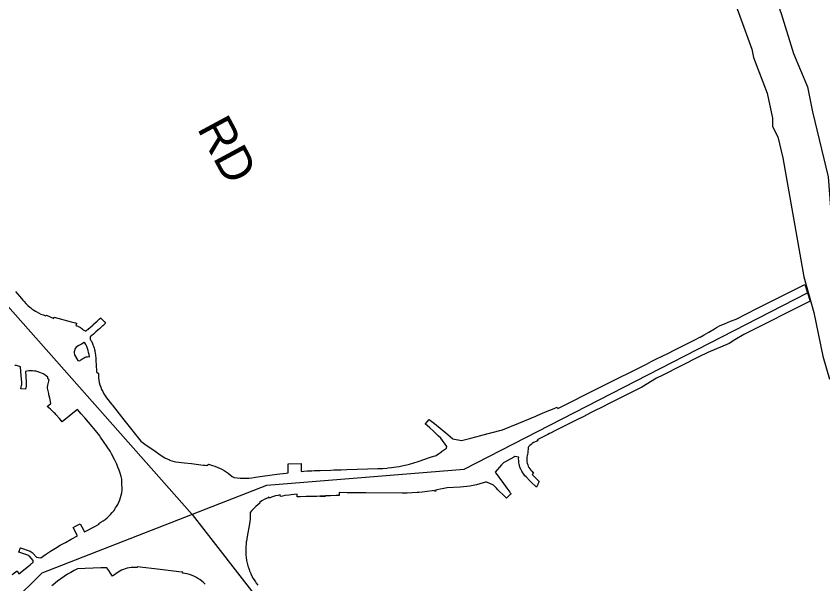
# Model space of a CAD drawing. Extents: x 1936118 to 1997618, y 780614 to 828614.
# Drawn here: x 1963667 to 1977726, y 800516 to 810402 of the extents above; entities that cross this region are included whole.
import ezdxf

# ---------------------------------------------------------------- set-up
doc = ezdxf.new("R2010")
doc.units = 0
for name, color, linetype in [('RD_EX_H2O_BlueLn', 7, 'Continuous'), ('RD_SHT_Misc3', 7, 'Continuous'), ('RD_SHT_Misc4', 7, 'Continuous')]:
    doc.layers.add(name, color=color, linetype=linetype)

msp = doc.modelspace()

# ---------------------------------------------------------------- linework, layer by layer
at = {"layer": 'RD_EX_H2O_BlueLn'}
for points in [[(1973253, 817137), (1973407, 816991), (1973584, 816594), (1973887, 815756), (1974339, 815098), (1974706, 814408), (1974918, 814125), (1975309, 813500), (1975457, 813315), (1975643, 812956), (1976517, 811570), (1976734, 811173), (1977001, 810446), (1977217, 809753), (1977458, 809171), (1977548, 808736), (1977820, 807606), (1977875, 806845), (1977998, 806260), (1978211, 805465), (1978363, 805022), (1978540, 804151), (1978567, 804110), (1978671, 803787)], [(1976212, 810593), (1976486, 809828), (1976516, 809681), (1976758, 809064), (1976848, 808628), (1976848, 808483), (1976942, 808300), (1977030, 807934), (1977392, 805863), (1977569, 805242), (1977724, 804480), (1977843, 804082)], [(1963654, 805609), (1963689, 805568), (1963692, 805566), (1963731, 805521), (1963787, 805456), (1963808, 805432), (1963839, 805398), (1963871, 805366), (1963905, 805336), (1963923, 805322), (1963941, 805307), (1963978, 805281), (1964006, 805264), (1964017, 805257), (1964057, 805235), (1964098, 805215), (1964140, 805198), (1964183, 805183), (1964198, 805195), (1964322, 805139), (1964332, 805162), (1964626, 805081), (1964700, 805061), (1964722, 805054), (1964721, 805051), (1964709, 805016), (1964709, 805016), (1964714, 805014), (1964716, 805014), (1964722, 805012), (1964724, 805011), (1964741, 805003), (1964749, 805000), (1964751, 804999), (1964766, 804991), (1964776, 804985), (1964788, 804978), (1964790, 804976), (1964799, 804970), (1964812, 804960), (1964821, 804953), (1964824, 804950), (1964833, 804942), (1964845, 804931), (1964880, 804914), (1964908, 804937), (1964920, 804948), (1964936, 804961), (1964966, 804989), (1965004, 805023), (1965012, 805030), (1965012, 805030), (1965077, 805089), (1965092, 805102), (1965117, 805124), (1965144, 805148), (1965151, 805139), (1965205, 805077), (1965205, 805077), (1965225, 805053), (1965200, 805030), (1965176, 805010), (1965175, 805009), (1965119, 804958), (1965093, 804935), (1965057, 804902), (1965026, 804874), (1965020, 804869), (1965013, 804863), (1965013, 804863), (1964989, 804842), (1964958, 804816), (1964958, 804813), (1964958, 804795), (1964958, 804778), (1964972, 804752), (1964978, 804740), (1964996, 804701), (1965002, 804687), (1965002, 804686), (1965012, 804661), (1965014, 804657), (1965014, 804655), (1965026, 804620), (1965031, 804600), (1965037, 804579), (1965040, 804565), (1965045, 804542), (1965045, 804537), (1965052, 804495), (1965052, 804488), (1965055, 804452), (1965057, 804416), (1965057, 804413), (1965069, 804227), (1965070, 804209), (1965105, 804177), (1965104, 804152), (1965103, 804105), (1965108, 804063), (1965117, 804022), (1965128, 803981), (1965141, 803941), (1965157, 803902), (1965166, 803885), (1965176, 803864), (1965196, 803827), (1965219, 803792), (1965244, 803758), (1965330, 803648), (1965343, 803632), (1965547, 803373), (1965843, 802998), (1965934, 802933), (1966065, 802842), (1966177, 802762), (1966259, 802710), (1966299, 802691), (1966340, 802673), (1966343, 802672), (1966382, 802658), (1966423, 802645), (1966450, 802641), (1966602, 802624), (1966721, 802610), (1966886, 802591), (1966931, 802585), (1966961, 802581), (1966992, 802576), (1967020, 802598), (1967088, 802578), (1967130, 802565), (1967172, 802549), (1967213, 802532), (1967252, 802512), (1967291, 802491), (1967329, 802467), (1967365, 802442), (1967400, 802415), (1967434, 802387), (1967468, 802367), (1967519, 802361), (1967570, 802357), (1967621, 802355), (1967672, 802356), (1967724, 802359), (1967775, 802365), (1967837, 802373), (1968211, 802424), (1968373, 802446), (1968408, 802450), (1968408, 802451), (1968410, 802561), (1968411, 802608), (1968633, 802610), (1968634, 802563), (1968634, 802562), (1968635, 802475), (1968683, 802478), (1968742, 802482), (1968819, 802487), (1968868, 802489), (1968909, 802490), (1968968, 802492), (1969154, 802498), (1969204, 802499), (1969330, 802503), (1969333, 802503), (1969429, 802506), (1969971, 802522), (1970050, 802525), (1970130, 802532), (1970149, 802534), (1970209, 802541), (1970288, 802552), (1970341, 802562), (1970342, 802562), (1970366, 802566), (1970444, 802583), (1970476, 802591), (1970522, 802602), (1970598, 802624), (1970674, 802648), (1970675, 802648), (1970888, 802720), (1970986, 802753), (1971026, 802779), (1971081, 802817), (1971083, 802818), (1971170, 802880), (1971172, 802907), (1971066, 803052), (1971022, 803096), (1970941, 803176), (1970877, 803233), (1970798, 803302), (1970805, 803310), (1970859, 803371), (1970868, 803381), (1970956, 803308), (1971057, 803225), (1971191, 803116), (1971279, 803043), (1971426, 803011), (1971591, 803054), (1971764, 803099), (1971785, 803104), (1972120, 803190), (1972141, 803196), (1972428, 803315), (1972724, 803439), (1972750, 803450), (1972840, 803487), (1972924, 803522), (1973012, 803559), (1973095, 803594), (1973109, 803570), (1973189, 803610), (1973270, 803651), (1973350, 803691), (1973431, 803731), (1973511, 803772), (1973592, 803812), (1973673, 803853), (1973753, 803893), (1973834, 803933), (1973914, 803974), (1973995, 804014), (1974088, 804061), (1974204, 804119), (1974328, 804181), (1974408, 804222), (1974489, 804262), (1974569, 804303), (1974650, 804343), (1974735, 804386), (1974829, 804433), (1974924, 804480), (1975035, 804536), (1975136, 804587), (1975251, 804645), (1975332, 804685), (1975412, 804725), (1975493, 804766), (1975581, 804810), (1975587, 804813), (1975659, 804855), (1975737, 804901), (1975835, 804957), (1975871, 804978), (1975934, 805015), (1976013, 805047), (1976118, 805089), (1976213, 805127), (1976576, 805309), (1977414, 805730), (1977507, 805441), (1977297, 805335), (1977061, 805217), (1976812, 805092), (1976347, 804859), (1976195, 804766), (1976091, 804702), (1975722, 804545), (1975566, 804467), (1974935, 804150), (1974935, 804150), (1974828, 804097), (1974571, 803940), (1974039, 803673), (1973945, 803626), (1973940, 803623), (1973689, 803498), (1973547, 803426), (1973501, 803403), (1973500, 803403), (1973498, 803402), (1973496, 803401), (1973475, 803390), (1973368, 803336), (1973255, 803280), (1973160, 803232), (1973056, 803180), (1972980, 803141), (1972980, 803141), (1972961, 803132), (1972931, 803117), (1972748, 803025), (1972757, 803008), (1972683, 802976), (1972662, 802962), (1972641, 802945), (1972622, 802927), (1972605, 802908), (1972599, 802900), (1972589, 802888), (1972586, 802799), (1972577, 802774), (1972571, 802748), (1972567, 802721), (1972566, 802706), (1972565, 802694), (1972566, 802668), (1972569, 802641), (1972574, 802615), (1972582, 802589), (1972582, 802588), (1972592, 802564), (1972605, 802540), (1972619, 802517), (1972635, 802496), (1972654, 802476), (1972679, 802450), (1972683, 802447), (1972675, 802439), (1972658, 802422), (1972665, 802415), (1972673, 802408), (1972674, 802407), (1972782, 802299), (1972760, 802254), (1972757, 802248), (1972735, 802198), (1972637, 802295), (1972622, 802311), (1972555, 802377), (1972533, 802400), (1972513, 802425), (1972495, 802451), (1972479, 802478), (1972467, 802502), (1972465, 802506), (1972452, 802536), (1972442, 802566), (1972438, 802585), (1972435, 802597), (1972429, 802628), (1972426, 802660), (1972425, 802692), (1972426, 802723), (1972360, 802735), (1972340, 802723), (1972158, 802623), (1972128, 802590), (1972013, 802463), (1972160, 802263), (1972219, 802182), (1972269, 802115), (1972278, 802102), (1972292, 802083), (1972283, 802075), (1972213, 802007), (1972188, 802032), (1972172, 802048), (1972064, 802156), (1972039, 802182), (1971986, 802234), (1971873, 802286), (1971866, 802289), (1971846, 802284), (1971746, 802256), (1971690, 802242), (1971633, 802229), (1971576, 802219), (1971519, 802211), (1971462, 802205), (1971404, 802201), (1971177, 802190), (1971092, 802170), (1971059, 802163), (1971006, 802152), (1970977, 802147), (1970980, 802132), (1970960, 802128), (1970957, 802143), (1970920, 802137), (1970833, 802124), (1970746, 802113), (1970687, 802108), (1970658, 802105), (1970571, 802099), (1970483, 802096), (1970395, 802096), (1969764, 802100), (1969756, 802101), (1969735, 802101), (1969435, 802103), (1969295, 802104), (1969297, 802056), (1969247, 802053), (1969145, 802049), (1969061, 802046), (1968959, 802041), (1968908, 802040), (1968807, 802038), (1968722, 802036), (1968617, 802034), (1968567, 802032), (1968565, 802079), (1968458, 802067), (1968423, 802062), (1968351, 802052), (1968311, 802045), (1968272, 802036), (1968266, 802064), (1968228, 802057), (1968190, 802048), (1968153, 802037), (1968116, 802025), (1968080, 802011), (1968074, 802025), (1968031, 802005), (1967989, 801983), (1967948, 801959), (1967908, 801933), (1967917, 801921), (1967879, 801893), (1967843, 801863), (1967808, 801830), (1967776, 801796), (1967745, 801761), (1967746, 801721), (1967746, 801680), (1967743, 801640), (1967739, 801600), (1967733, 801560), (1967695, 801340), (1967682, 801260), (1967679, 801244), (1967675, 801213), (1967670, 801165), (1967668, 801117), (1967668, 801069), (1967670, 801030), (1967671, 801020), (1967676, 800973), (1967683, 800925), (1967693, 800878), (1967705, 800831), (1967706, 800828), (1967720, 800785), (1967728, 800764), (1967737, 800740), (1967755, 800696), (1967758, 800691), (1967777, 800652), (1967800, 800610), (1967825, 800569), (1967839, 800549), (1967853, 800530), (1967882, 800492)], [(1963600, 800676), (1963684, 800742), (1963716, 800693), (1963882, 800825), (1963914, 800850), (1963938, 800870), (1963939, 800871), (1963967, 800893), (1963965, 800925), (1963900, 800997), (1963891, 801005), (1963881, 801012), (1963870, 801016), (1963839, 801026), (1963716, 801068), (1963717, 801071), (1963719, 801078), (1963740, 801135), (1963738, 801135), (1963741, 801144), (1963743, 801143), (1963895, 801092), (1963913, 801085), (1963930, 801075), (1963945, 801064), (1963959, 801050), (1964023, 800979), (1964060, 800976), (1964099, 800972), (1964182, 801029), (1964266, 801085), (1964351, 801138), (1964437, 801189), (1964525, 801238), (1964624, 801292), (1964624, 801292), (1964738, 801353), (1964660, 801498), (1964701, 801520), (1964783, 801564), (1964812, 801511), (1964861, 801420), (1964908, 801445), (1965114, 801557), (1965109, 801566), (1965146, 801588), (1965182, 801611), (1965217, 801637), (1965251, 801664), (1965283, 801693), (1965313, 801724), (1965341, 801756), (1965368, 801790), (1965393, 801826), (1965401, 801838), (1965416, 801862), (1965437, 801900), (1965456, 801939), (1965473, 801979), (1965487, 802019), (1965500, 802061), (1965510, 802102), (1965518, 802145), (1965510, 802295), (1965508, 802334), (1965507, 802337), (1965495, 802388), (1965479, 802442), (1965461, 802494), (1965442, 802547), (1965420, 802598), (1965380, 802682), (1965332, 802778), (1965325, 802791), (1965307, 802825), (1965138, 803073), (1965126, 803091), (1965051, 803185), (1964991, 803259), (1964929, 803333), (1964866, 803405), (1964802, 803476), (1964735, 803550), (1964716, 803535), (1964716, 803535), (1964470, 803340), (1964424, 803393), (1964358, 803468), (1964345, 803483), (1964330, 803497), (1964283, 803539), (1964264, 803556), (1964209, 803606), (1964271, 803655), (1964258, 803721), (1964252, 803748), (1964243, 803793), (1964239, 803809), (1964235, 803831), (1964230, 803856), (1964216, 803922), (1964213, 803938), (1964222, 803977), (1964238, 804046), (1964243, 804065), (1964231, 804078), (1964218, 804091), (1964219, 804117), (1964197, 804135), (1964170, 804154), (1964141, 804171), (1964112, 804186), (1964082, 804199), (1964050, 804209), (1964045, 804210), (1964018, 804217), (1963986, 804222), (1963953, 804225), (1963920, 804226), (1963887, 804224), (1963854, 804220), (1963830, 804215), (1963844, 804036), (1963845, 804010), (1963844, 803984), (1963841, 803958), (1963832, 803904), (1963752, 803910), (1963762, 803970), (1963764, 803990), (1963765, 804010), (1963765, 804010), (1963764, 804029), (1963755, 804138), (1963743, 804293), (1963673, 804320), (1963643, 804320)], [(1966961, 800510), (1966938, 800532), (1966931, 800538), (1966901, 800565), (1966868, 800589), (1966834, 800611), (1966799, 800632), (1966763, 800650), (1966725, 800665), (1966687, 800679), (1966648, 800690), (1966608, 800698), (1966568, 800704), (1966570, 800719), (1966501, 800728), (1966180, 800766), (1965778, 800815), (1965776, 800800), (1965741, 800803), (1965739, 800803), (1965707, 800803), (1965672, 800801), (1965638, 800797), (1965604, 800789), (1965570, 800780), (1965538, 800768), (1965506, 800753), (1965476, 800737), (1965447, 800718), (1965349, 800650), (1965310, 800705), (1965281, 800746), (1965281, 800747), (1965246, 800797), (1965143, 800794), (1964737, 800780), (1964715, 800768), (1964677, 800749), (1964618, 800716), (1964560, 800682), (1964503, 800645), (1964447, 800606), (1964408, 800577), (1964394, 800566), (1964345, 800526), (1964341, 800523), (1964290, 800479)]]:
    msp.add_lwpolyline(points, dxfattribs=at)
for points in [[(1964890, 804467), (1964910, 804471), (1964931, 804474), (1964944, 804471), (1964938, 804508), (1964931, 804544), (1964922, 804580), (1964910, 804615), (1964897, 804650), (1964882, 804683), (1964865, 804716), (1964851, 804719), (1964807, 804691), (1964761, 804664), (1964714, 804638), (1964694, 804613), (1964681, 804555), (1964678, 804539), (1964683, 804506), (1964743, 804407), (1964778, 804402), (1964795, 804417), (1964813, 804430), (1964832, 804442), (1964852, 804453), (1964871, 804461)], [(1968959, 802041), (1969061, 802045), (1968958, 802041)]]:
    msp.add_lwpolyline(points, close=True, dxfattribs=at)
at = {"layer": 'RD_SHT_Misc4'}
for p, q in [((1959396, 810005), (1966734, 801722)), ((1971476, 802516), (1977461, 805585)), ((1968039, 802236), (1971476, 802516)), ((1964119, 800706), (1968039, 802236)), ((1966734, 801722), (1971705, 795370)), ((1956667, 793363), (1964119, 800706))]:
    msp.add_line(p, q, dxfattribs=at)

# ---------------------------------------------------------------- texts
at = {"layer": 'RD_SHT_Misc3'}
msp.add_text('RD', height=600, rotation=298.3208, dxfattribs=at).set_placement((1966813, 808449))

doc.saveas('drawing.dxf')
